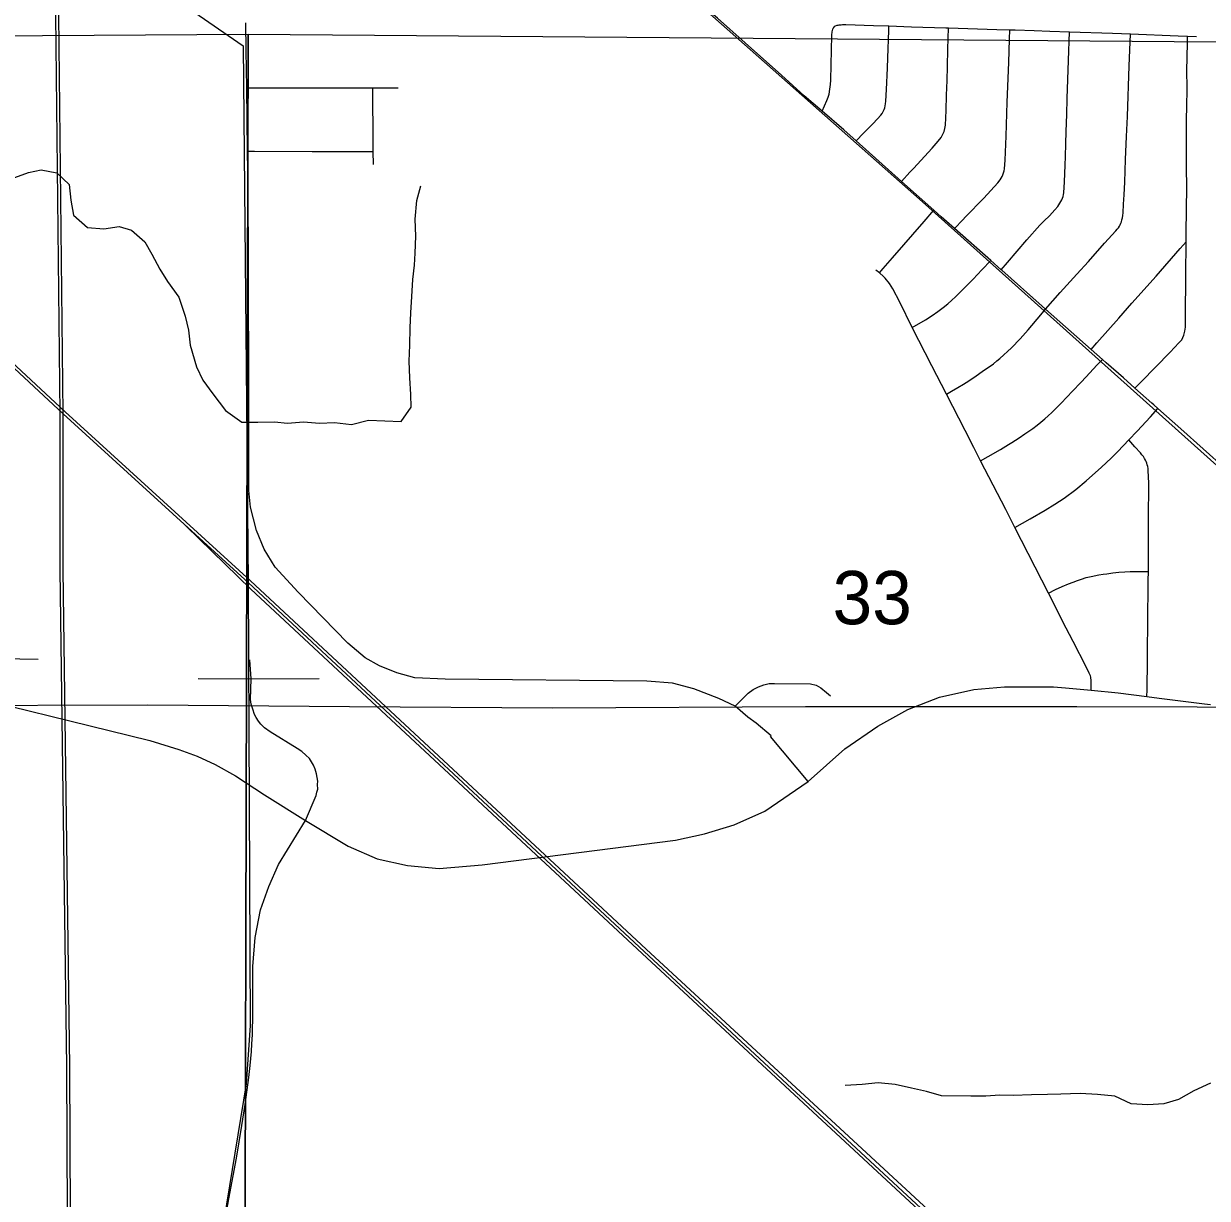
# Model space of a CAD drawing. Extents: x 0 to 40.2, y 0 to 22.
# Drawn here: x 4.597 to 5.526, y 16.354 to 17.276 of the extents above; entities that cross this region are included whole.
import ezdxf

# ---------------------------------------------------------------- set-up
doc = ezdxf.new("R2010")
doc.units = 0
for name, color, linetype in [('GM_X_City_Street', 7, 'Continuous'), ('GM_X_Corporation', 7, 'Continuous'), ('GM_X_Major_Lake', 7, 'Continuous'), ('GM_X_Major_River', 7, 'Continuous'), ('GM_X_Minor_Lake', 7, 'Continuous'), ('GM_X_Rail_Line', 7, 'Continuous'), ('GM_X_Unincorporated_Location', 7, 'Continuous')]:
    doc.layers.add(name, color=color, linetype=linetype)

msp = doc.modelspace()

# ---------------------------------------------------------------- linework, layer by layer
at = {"layer": 'GM_X_Corporation'}
for points in [[(4.77298, 17.26753), (4.77053, 16.2552), (4.73985, 16.25627), (3.77479, 16.25485), (3.76422, 17.2609)], [(4.77298, 17.26753), (5.76443, 17.25959), (5.74842, 16.25686), (4.77053, 16.2552)]]:
    msp.add_lwpolyline(points, close=True, dxfattribs=at)
at = {"layer": 'GM_X_Major_Lake'}
for points in [[(5.19169, 17.23518), (5.16328, 17.26059), (5.14142, 17.27994), (5.13684, 17.28392), (5.12082, 17.29787), (5.10624, 17.31056), (5.09568, 17.31984)], [(5.44673, 17.00952), (5.44372, 17.01217), (5.43488, 17.01996), (5.39902, 17.05156), (5.39635, 17.05392), (5.36483, 17.08209), (5.36433, 17.08252), (5.35613, 17.08974), (5.32764, 17.11478), (5.31719, 17.12396), (5.31136, 17.12917), (5.28605, 17.15174), (5.25032, 17.18362), (5.24064, 17.19224), (5.22369, 17.20694), (5.20963, 17.21912), (5.19169, 17.23518)], [(5.48411, 16.97635), (5.48254, 16.97775), (5.46925, 16.98959), (5.46025, 16.9976), (5.44673, 17.00952)], [(5.62241, 16.85317), (5.61791, 16.85715), (5.61248, 16.86195), (5.61128, 16.86303), (5.60244, 16.87093), (5.59485, 16.87772), (5.57314, 16.89725), (5.54749, 16.91986), (5.54029, 16.92629), (5.5053, 16.9575), (5.48725, 16.97355), (5.48411, 16.97635)]]:
    msp.add_lwpolyline(points, dxfattribs=at)
at = {"layer": 'GM_X_Major_River'}
for points in [[(4.14708, 17.41668), (4.15582, 17.40861), (4.32394, 17.25012), (4.51417, 17.0781), (4.62927, 16.97109), (4.77483, 16.83834), (5.0856, 16.54914), (5.61128, 16.06321), (6.03991, 15.66631), (6.16984, 15.5443), (6.56686, 15.1758), (7.03827, 14.73746), (7.41547, 14.38724), (7.72366, 14.1)], [(4.59498, 15.70159), (4.59656, 15.70372), (4.61052, 15.72266), (4.61811, 15.7396), (4.62426, 15.75717), (4.63093, 15.78112), (4.63373, 15.80092), (4.63465, 15.82821), (4.6339, 15.96965), (4.63233, 16.10669), (4.63064, 16.45685), (4.62545, 16.84695), (4.62537, 16.96937), (4.62178, 17.30668), (4.62122, 17.3587), (4.62062, 17.42396)], [(4.59686, 15.70021), (4.59843, 15.70234), (4.61254, 15.72149), (4.62028, 15.73875), (4.62648, 15.75648), (4.63322, 15.78065), (4.63606, 15.80072), (4.63698, 15.82818), (4.63623, 15.96967), (4.63466, 16.10671), (4.63297, 16.45687), (4.62777, 16.84697), (4.62769, 16.96938), (4.62411, 17.3067), (4.62355, 17.35873), (4.62295, 17.42396)], [(4.97994, 17.42091), (5.30245, 17.13578), (5.95038, 16.5554), (6.62714, 15.93274), (7.15702, 15.44764), (7.76806, 14.87866), (8.24495, 14.44186), (8.61841, 14.1)], [(4.1455, 17.41498), (4.15423, 17.40692), (4.32235, 17.24842), (4.5126, 17.07639), (4.62769, 16.96938), (4.77325, 16.83664), (5.08401, 16.54745), (5.60901, 16.06047), (6.03765, 15.66283), (6.16779, 15.54229), (6.56535, 15.17287), (7.03604, 14.73583), (7.41439, 14.3845), (7.72091, 14.1)], [(4.62333, 17.35928), (4.67721, 17.32197), (4.76914, 17.2583), (4.77303, 16.83719)], [(4.72429, 16.88129), (4.77518, 16.83167), (5.08242, 16.54575), (5.60741, 16.05878), (6.03523, 15.66065), (6.1639, 15.54197), (6.56367, 15.17142), (7.03343, 14.73438), (7.41136, 14.38359), (7.71741, 14.1)], [(4.77303, 16.83719), (4.77463, 16.48922), (4.77158, 16.4434), (4.7496, 16.30901), (4.74166, 16.26931), (4.73921, 16.22471), (4.73994, 15.78144), (4.74339, 15.18362)]]:
    msp.add_lwpolyline(points, dxfattribs=at)
at = {"layer": 'GM_X_Minor_Lake'}
for points in [[(4.58683, 17.15383), (4.60053, 17.15892), (4.6104, 17.16103), (4.62285, 17.15856), (4.63254, 17.14929), (4.63386, 17.13713), (4.63594, 17.12534), (4.64676, 17.11568), (4.65961, 17.11471), (4.67174, 17.11641), (4.68153, 17.1136), (4.69197, 17.10432), (4.6975, 17.09475), (4.70374, 17.08289), (4.70964, 17.07331), (4.71853, 17.06102), (4.72359, 17.04615), (4.72606, 17.0351), (4.72739, 17.02332), (4.73241, 17.00617), (4.73754, 16.99584), (4.74532, 16.98509), (4.75532, 16.97203), (4.76804, 16.96272), (4.78053, 16.9629), (4.79377, 16.96306), (4.80397, 16.96214), (4.81647, 16.96308), (4.82894, 16.96212), (4.84068, 16.96269), (4.85427, 16.96095), (4.86757, 16.96453), (4.89328, 16.96336), (4.90102, 16.97461), (4.9008, 16.98448), (4.89988, 16.99777), (4.89932, 17.01068), (4.8999, 17.02319), (4.90012, 17.03685), (4.90068, 17.0486), (4.90164, 17.06148), (4.90223, 17.07475), (4.90355, 17.08611), (4.90408, 17.09559), (4.90467, 17.10886), (4.90412, 17.12215), (4.90549, 17.13692), (4.9087, 17.14825)], [(5.70689, 16.73852), (5.42354, 16.7393), (5.21054, 16.73932), (5.0119, 16.73836), (4.85265, 16.73941), (4.69415, 16.74083), (4.52087, 16.74021)], [(5.52856, 16.44395), (5.51561, 16.43809), (5.50339, 16.43108), (5.49199, 16.42785), (5.47949, 16.42691), (5.46626, 16.42788), (5.45349, 16.43378), (5.4399, 16.43514), (5.42629, 16.43574), (5.41114, 16.43523), (5.40055, 16.43502), (5.38806, 16.43484), (5.37368, 16.43431), (5.36308, 16.43448), (5.3521, 16.4339), (5.34037, 16.43371), (5.3173, 16.43408), (5.30562, 16.43731), (5.29394, 16.44015), (5.28112, 16.44301), (5.26753, 16.44437), (5.25502, 16.44306), (5.24176, 16.44213)]]:
    msp.add_lwpolyline(points, dxfattribs=at)
at = {"layer": 'GM_X_Rail_Line'}
msp.add_line((4.77253, 17.17558), (4.77188, 17.22524), dxfattribs=at)
for points in [[(4.77188, 17.22524), (4.77148, 17.25458), (4.77126, 17.27642)], [(4.7736, 16.92803), (4.7736, 16.95873), (4.77345, 17.00284), (4.77348, 17.01398), (4.77332, 17.055), (4.77329, 17.09728), (4.77314, 17.13519), (4.77273, 17.16065), (4.77253, 17.17558)], [(5.21273, 16.68089), (5.18317, 16.71615), (5.18371, 16.71669), (5.17178, 16.72645), (5.16527, 16.73133), (5.15551, 16.74001), (5.14249, 16.74598), (5.12297, 16.75357), (5.10615, 16.75791), (5.08609, 16.75954), (4.92772, 16.76116), (4.90385, 16.76225), (4.88975, 16.76605), (4.87619, 16.77147), (4.8648, 16.77798), (4.85124, 16.78937), (4.81219, 16.8295), (4.79429, 16.84903), (4.78562, 16.86313), (4.77965, 16.87777), (4.77477, 16.89621), (4.77368, 16.90923), (4.7736, 16.92011), (4.7736, 16.92803)], [(4.52312, 16.75548), (4.69574, 16.7129), (4.7185, 16.70597), (4.73302, 16.7007), (4.7472, 16.6941), (4.76304, 16.68519), (4.7858, 16.67034), (4.81795, 16.65011)], [(5.21273, 16.68089), (5.24147, 16.70639), (5.26751, 16.72428), (5.29083, 16.7373), (5.31578, 16.74706), (5.3429, 16.75303), (5.36676, 16.7552), (5.4053, 16.75501), (5.41462, 16.75439), (5.43485, 16.75259)], [(5.43485, 16.75259), (5.45611, 16.75026), (5.47871, 16.74742)], [(5.47871, 16.74742), (5.48818, 16.74623), (5.52393, 16.74171), (5.52852, 16.74125)], [(4.81795, 16.65011), (4.85151, 16.62991), (4.87429, 16.62015), (4.89816, 16.61473), (4.92311, 16.61256), (4.95673, 16.61527), (5.1086, 16.63479), (5.13137, 16.63967), (5.1547, 16.64673), (5.17856, 16.65757), (5.21273, 16.68089)], [(4.77672, 16.50803), (4.77679, 16.53557), (4.77857, 16.55832), (4.78263, 16.58002), (4.78914, 16.59846), (4.79674, 16.61554), (4.81795, 16.65011)], [(4.74194, 16.25496), (4.74357, 16.26804), (4.7467, 16.28894), (4.75359, 16.32941), (4.75788, 16.35327), (4.76375, 16.3851), (4.7681, 16.41088), (4.77061, 16.42727), (4.77356, 16.44841), (4.77455, 16.45777), (4.7752, 16.46338), (4.77569, 16.46881), (4.77602, 16.47473), (4.77632, 16.48203), (4.77669, 16.49885), (4.77672, 16.50803)]]:
    msp.add_lwpolyline(points, dxfattribs=at)
at = {"layer": 'GM_X_Unincorporated_Location'}
for points in [[(5.22369, 17.20694), (5.22741, 17.21542), (5.22853, 17.21795), (5.22924, 17.22038), (5.22984, 17.22413), (5.23025, 17.22788), (5.23045, 17.23123), (5.23073, 17.24326), (5.23125, 17.26627), (5.23135, 17.26748), (5.23149, 17.26851), (5.23162, 17.26938), (5.23178, 17.27028), (5.23214, 17.27146), (5.23242, 17.27208), (5.23278, 17.2727), (5.23365, 17.27363)], [(5.23365, 17.27363), (5.23419, 17.27394), (5.23547, 17.27439), (5.23615, 17.27453), (5.23697, 17.27466), (5.23786, 17.27477), (5.23873, 17.27483), (5.23975, 17.27489), (5.24223, 17.27489), (5.26393, 17.27428), (5.27603, 17.27388), (5.29376, 17.27329), (5.32078, 17.27246), (5.32282, 17.27239), (5.36087, 17.27116), (5.37095, 17.27086), (5.37515, 17.27073), (5.39005, 17.27023), (5.40247, 17.26985), (5.41777, 17.26924), (5.45157, 17.26812), (5.46567, 17.26765), (5.50312, 17.26622), (5.5106, 17.26591), (5.51769, 17.26561)], [(5.25032, 17.18362), (5.25615, 17.18961), (5.26343, 17.19712), (5.26714, 17.20097), (5.26973, 17.20375), (5.27067, 17.20503), (5.27135, 17.20616), (5.27187, 17.20721), (5.27233, 17.20836), (5.27285, 17.2097), (5.27323, 17.2112), (5.27353, 17.21285), (5.27377, 17.21476), (5.27433, 17.22399), (5.27503, 17.24072), (5.27522, 17.24878), (5.27591, 17.27021), (5.27603, 17.27388)], [(5.28605, 17.15174), (5.29253, 17.15899), (5.29554, 17.16235), (5.30401, 17.17145), (5.30995, 17.17785), (5.31488, 17.1834), (5.31705, 17.18635), (5.31828, 17.18841), (5.31945, 17.19111), (5.32005, 17.19334), (5.3204, 17.19586), (5.32109, 17.20753), (5.3214, 17.21965), (5.32176, 17.23107), (5.32211, 17.24213), (5.32238, 17.25564), (5.32282, 17.27239)], [(5.32135, 16.98485), (5.32532, 16.98706), (5.33031, 16.98994), (5.33465, 16.99257), (5.33896, 16.99528), (5.34469, 16.99915), (5.34941, 17.00254), (5.35811, 17.00875), (5.36086, 17.01092), (5.36316, 17.01284), (5.37223, 17.02122), (5.3792, 17.02838), (5.38547, 17.03535), (5.39537, 17.04719), (5.39902, 17.05156), (5.41043, 17.06456), (5.42377, 17.07912), (5.43269, 17.08886), (5.44529, 17.10346), (5.45417, 17.11301), (5.4553, 17.11427), (5.45623, 17.11543), (5.45704, 17.11659), (5.45763, 17.1177), (5.4582, 17.11898), (5.45859, 17.12014), (5.45907, 17.12165), (5.45943, 17.12326), (5.45971, 17.12513), (5.45996, 17.12707), (5.46027, 17.13394), (5.46079, 17.14125), (5.46129, 17.15119), (5.46186, 17.16916), (5.46262, 17.18716), (5.46329, 17.20269), (5.46468, 17.24244), (5.46541, 17.26105), (5.46567, 17.26765)], [(5.32764, 17.11478), (5.33418, 17.1217), (5.33631, 17.12396), (5.35059, 17.13874), (5.36155, 17.15069), (5.36357, 17.1532), (5.3643, 17.1543), (5.36499, 17.15561), (5.36556, 17.15698), (5.36606, 17.15852), (5.36646, 17.16004), (5.36674, 17.1617), (5.36742, 17.16859), (5.36811, 17.18731), (5.36899, 17.21393), (5.3703, 17.2453), (5.37076, 17.2634), (5.37095, 17.27086)], [(5.36433, 17.08252), (5.3691, 17.08811), (5.3844, 17.10603), (5.39471, 17.11744), (5.39812, 17.1209), (5.40213, 17.1249), (5.40628, 17.12942), (5.40862, 17.13222), (5.41041, 17.13477), (5.41187, 17.13726), (5.41251, 17.13866), (5.41294, 17.14001), (5.41328, 17.14147), (5.4135, 17.14293), (5.41404, 17.15155), (5.4145, 17.16455), (5.41479, 17.17135), (5.41507, 17.18124), (5.41537, 17.19111), (5.41578, 17.20443), (5.41617, 17.21702), (5.41708, 17.24664), (5.41777, 17.26924)], [(5.46925, 16.98959), (5.47408, 16.99455), (5.49682, 17.01785), (5.50383, 17.02503), (5.50595, 17.02748), (5.50698, 17.02923), (5.50771, 17.03107), (5.5085, 17.03421), (5.50891, 17.0374), (5.50907, 17.04178), (5.50904, 17.04553), (5.50928, 17.07831), (5.50947, 17.10428), (5.50952, 17.10956), (5.5098, 17.13132), (5.5099, 17.14565), (5.50973, 17.1643), (5.50983, 17.19477), (5.51008, 17.21652), (5.51019, 17.21838), (5.51021, 17.22584), (5.51011, 17.23828), (5.51051, 17.26062), (5.5106, 17.26591)], [(4.77188, 17.22524), (4.7918, 17.22527), (4.81714, 17.2253), (4.84136, 17.22537), (4.87097, 17.22521), (4.87358, 17.2252), (4.89091, 17.22518)], [(4.87134, 17.16504), (4.87123, 17.17535), (4.8711, 17.1866), (4.87098, 17.21991), (4.87097, 17.22521)], [(4.77253, 17.17558), (4.77809, 17.17555), (4.82323, 17.17533), (4.86705, 17.17534), (4.87123, 17.17535)], [(5.2688, 17.08004), (5.27166, 17.08338), (5.27899, 17.09197), (5.30377, 17.12045), (5.31136, 17.12917)], [(5.43488, 17.01996), (5.43938, 17.02504), (5.45664, 17.04455), (5.46688, 17.05623), (5.48597, 17.07751), (5.50489, 17.09907), (5.50947, 17.10428)], [(5.43485, 16.75259), (5.43488, 16.75673), (5.4349, 16.75964), (5.43484, 16.76071), (5.43472, 16.76179), (5.43452, 16.76274), (5.43425, 16.76365), (5.43389, 16.7647), (5.43344, 16.76578), (5.43096, 16.77084), (5.42069, 16.79075), (5.41227, 16.80672), (5.40602, 16.81958), (5.40134, 16.82875), (5.37492, 16.88007), (5.36784, 16.89431), (5.348, 16.93262), (5.34275, 16.94293), (5.33598, 16.95623), (5.32135, 16.98485), (5.30988, 17.00713), (5.29435, 17.03727), (5.28461, 17.05706), (5.27908, 17.06742), (5.27647, 17.07158), (5.2755, 17.07301), (5.2743, 17.07452), (5.27306, 17.07594), (5.27186, 17.07721), (5.2688, 17.08004), (5.26591, 17.08224)], [(5.29435, 17.03727), (5.30474, 17.04311), (5.31011, 17.04659), (5.31461, 17.04977), (5.31859, 17.05279), (5.3224, 17.0558), (5.32547, 17.05851), (5.32827, 17.06113), (5.33371, 17.06643), (5.34212, 17.07518), (5.34905, 17.08238), (5.35613, 17.08974)], [(5.348, 16.93262), (5.35406, 16.93596), (5.3636, 16.9414), (5.37009, 16.94521), (5.37264, 16.9469), (5.3783, 16.95064), (5.3829, 16.95377), (5.38897, 16.95797), (5.39243, 16.96051), (5.39533, 16.96273), (5.39852, 16.96542), (5.40122, 16.96778), (5.40393, 16.97031), (5.40606, 16.97257), (5.41127, 16.97787), (5.42031, 16.98722), (5.42679, 16.99389), (5.43109, 16.9984), (5.43946, 17.00752), (5.44372, 17.01217)], [(5.37492, 16.88007), (5.38709, 16.88692), (5.3989, 16.89374), (5.40641, 16.89837), (5.41367, 16.90324), (5.42273, 16.90999), (5.43085, 16.91671), (5.44308, 16.92742), (5.45049, 16.93462), (5.45572, 16.93977), (5.46447, 16.9489), (5.47112, 16.95584), (5.48139, 16.96712), (5.48725, 16.97355)], [(5.47871, 16.74742), (5.47878, 16.75278), (5.47907, 16.77598), (5.47942, 16.81259), (5.47968, 16.82998), (5.47971, 16.83865), (5.47984, 16.84551), (5.47992, 16.85756), (5.47995, 16.86965), (5.47996, 16.87772), (5.47993, 16.8858), (5.48003, 16.89572), (5.48013, 16.90564), (5.48008, 16.91485), (5.47973, 16.92494), (5.47962, 16.92656), (5.47932, 16.92812), (5.47898, 16.92944), (5.47857, 16.93065), (5.47806, 16.93191), (5.47753, 16.93303), (5.47679, 16.93439), (5.47588, 16.9358), (5.47478, 16.93727), (5.47351, 16.9388), (5.4693, 16.94351), (5.46447, 16.9489)], [(5.40134, 16.82875), (5.40702, 16.83148), (5.41206, 16.83373), (5.41697, 16.83588), (5.42065, 16.83731), (5.42413, 16.83865), (5.4273, 16.83967), (5.43109, 16.8408), (5.43488, 16.84172), (5.44081, 16.84295), (5.44419, 16.84346), (5.44719, 16.84391), (5.45197, 16.84459), (5.45657, 16.845), (5.46128, 16.84541), (5.46547, 16.84562), (5.46879, 16.84574), (5.47243, 16.84572), (5.47652, 16.84562), (5.47984, 16.84551)], [(4.52312, 16.75548), (4.53068, 16.76766), (4.53232, 16.76993), (4.53459, 16.77195), (4.53673, 16.77346), (4.54052, 16.77586), (4.54355, 16.77687), (4.54708, 16.77763), (4.55036, 16.77788), (4.60826, 16.77674)], [(4.81795, 16.65011), (4.82638, 16.66974), (4.82692, 16.67246), (4.82765, 16.67464), (4.82747, 16.67846), (4.82765, 16.681), (4.82656, 16.68681), (4.82565, 16.69045), (4.82438, 16.69353), (4.82274, 16.69626), (4.82129, 16.6988), (4.81838, 16.70135), (4.81529, 16.70425), (4.81148, 16.70661), (4.79022, 16.71988), (4.78586, 16.72296), (4.78296, 16.72587), (4.78114, 16.72823), (4.77932, 16.73114), (4.77787, 16.7335), (4.7766, 16.7375), (4.77551, 16.74149), (4.77496, 16.74513), (4.77533, 16.7613), (4.77424, 16.77637)], [(4.73382, 16.76166), (4.77533, 16.7613), (4.82864, 16.76174)], [(5.15551, 16.74001), (5.16564, 16.75012), (5.16945, 16.75303), (5.17381, 16.75503), (5.17781, 16.75666), (5.18217, 16.75775), (5.18635, 16.75775), (5.21451, 16.75757), (5.21887, 16.75648), (5.22268, 16.7543), (5.22704, 16.75067), (5.23031, 16.74794)]]:
    msp.add_lwpolyline(points, dxfattribs=at)

# ---------------------------------------------------------------- texts
at = {"layer": 'GM_X_City_Street'}
msp.add_text('33', height=0.041856, rotation=0.00001, dxfattribs=at).set_placement((5.23185, 16.8042))

doc.saveas('drawing.dxf')
